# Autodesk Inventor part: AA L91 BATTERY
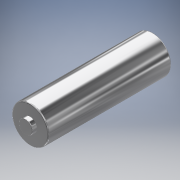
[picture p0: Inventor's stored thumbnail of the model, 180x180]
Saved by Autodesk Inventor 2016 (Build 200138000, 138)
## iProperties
Created: 2008-04
Part Number: AA L91 BATTERY
Document SubType Name: Modeling
Designer: J.HARRIS
Mass: 8.22606 g
Surface Area: 25.9035 cm^2
Volume: 8.22606 cm^3
Density: 1 g/cm^3
Material: Generic
Appearance: Chrome - Polished
Author: J.HARRIS
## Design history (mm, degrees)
sketch "Sketch1"
  geometry: L1 (0, 10.152)-(0, -10.152) reference; L2 (-10.152, 0)-(10.152, 0) reference; C1 r 7.252 at (0, 0)
  constraints: 2 midpoint, 1 centre point
  dimensions: "d0" = 14.5034 diameter of C1
extrude "Extrusion1" new body sketch "Sketch1" stored distance "d1" = 50.7492; taper "d2" = 0 deg
sketch "Sketch2"
  geometry: C1 r 7.252 at (0, 0) reference; C2 r 2.756 at (0, 0)
  constraints: 1 centre point, 1 coincident
  dimensions: "d3" = 5.5118 diameter of C2
extrude "Extrusion2" cut sketch "Sketch2" distance "d4" = 1.778; taper "d5" = 0 deg
sketch "Sketch3"
  geometry: C1 r 7.252 at (0, 0) reference; C2 r 4.572 at (0, 0)
  constraints: 1 centre point, 1 coincident
  dimensions: "d6" = 9.144 diameter of C2
extrude "Extrusion3" cut sketch "Sketch3" distance "d7" = 0.5588; taper "d8" = 0 deg
fillet "Fillet1" dims "d9" = 0.508
fillet "Fillet2" dims "d10" = 0.254
workplane "Work Plane1"
sketch "Sketch4"
  geometry: L1 (7.252, -24.308)-(7.252, 23.089) reference; L2 (7.252, 23.089)-(-7.252, 23.089) reference; L3 (-22.763, 23.089)-(22.763, 23.089); L4 (22.763, 23.089)-(22.763, -24.308); L5 (22.763, -24.308)-(-22.763, -24.308); L6 (-22.763, -24.308)-(-22.763, 23.089); 6 further points; 1 other entity
  constraints: 3 coincident, 2 midpoint, 2 vertical alignment, 1 collinear, 2 other
  dimensions: "d14" = 47.3964 distance of L1.start L1.end (derived); "d28" = 47.3964 distance of L3.end L4.end (= d14)
feature "Decal1" sketch "Sketch4"
chamfer "Chamfer2" distance "d37" = 0.5588; stored, may be unused: second distance "d38" = 3.175, angle "d39" = 45 deg
fillet "Fillet3" dims "d40" = 0.508, "d41" = 0.254
sketch "Sketch5"
  geometry: C1 r 3.803 at (0, 0) reference; C2 r 1.651 at (0, 0)
  constraints: 1 centre point, 1 coincident
  dimensions: "d42" = 3.302 diameter of C2
extrude "Extrusion4" cut sketch "Sketch5" distance "d43" = 0.0762; taper "d44" = 0 deg
chamfer "Chamfer3" distance "d45" = 0.0762; stored, may be unused: second distance "d46" = 3.175, angle "d47" = 45 deg
fillet "Fillet4" dims "d48" = 0.0762
sketch "Sketch6"
  geometry: L1 (-7.252, -24.308)-(-7.252, 23.089) reference; L2 (-7.252, 23.089)-(39.264, 23.089); L3 (39.264, 23.089)-(39.264, -25.337); L4 (39.264, -25.337)-(-7.252, -25.337); L5 (-7.252, -25.337)-(-7.252, 23.089); 1 further point; 1 other entity
  constraints: 1 point on line, 2 other
feature "Decal2" sketch "Sketch6"
body "Solid1"
node "Image5"
node "Image6"
